(* Logix 5000 project; controller CIP_Sync_Essentials_Sample_Project_2_1 vendor 1 type 14 code 156 rev 34.11; software revision 34.01 *)

TASK IOTask (task) : IOProgram
TASK MainTask (periodic, rate 3 ms, priority 10, watchdog 500 ms) : MainProgram

MODULES
   Local : vendor 1 type 14 code 156 (Compact 0, rev 34.11)
      Essentials_1 : vendor 452 type 43 code 30 (Ethernet 192.168.1.12, rev 1.3, StandardDataDriven RPI 3 ms)
END_MODULES

TYPE CIP_AxisInputData :
STRUCT
   Data : SINT[10];
END_STRUCT
END_TYPE

TYPE CIP_AxisOutputData :
STRUCT
   Data : SINT[14];
END_STRUCT
END_TYPE

TYPE CIP_Control :
STRUCT
   Switch_On : BOOL;
   Disable_Voltage : BOOL;
   Quick_Stop : BOOL;
   Enable_Operation : BOOL;
   Op_Mode_Specific_4 : BOOL;   // Home Start or Follow Position bit, depending on on whether bit 11 (Mode Home) or bit 12 (C
   Op_Mode_Specific_5 : BOOL;   // Unused
   Op_Mode_Specific_6 : BOOL;   // Unused
   Reset_Fault : BOOL;
   Pause_Halt : BOOL;
   Op_Mode_Specific_9 : BOOL;   // Unused
   Reserved_10 : BOOL;
   Manu_Specific_11 : BOOL;   // Mode Home bit
   Manu_Specific_12 : BOOL;   // Mode Cyclic Position bit
   Manu_Specific_13 : BOOL;   // Unused
   Manu_Specific_14 : BOOL;   // Unused
   Manu_Specific_15 : BOOL;   // Unused
END_STRUCT
END_TYPE

TYPE CIP_DynamicMap :
STRUCT
   Input : CIP_MapInputData;   // Map data from the drive
   Output : CIP_MapOutputData;   // Map data to the drive
END_STRUCT
END_TYPE

TYPE CIP_MapInputData :   // Map data received from the drive
STRUCT
   Data : SINT[40];
END_STRUCT
END_TYPE

TYPE CIP_MapOutputData :   // Map data going to drive
STRUCT
   Data : SINT[32];
END_STRUCT
END_TYPE

TYPE CIP_Status :   // All connections to the drive ethernet module are established and data is successfully transferring.
STRUCT
   Ready_To_Switch_On : BOOL;
   Switched_On : BOOL;
   Operation_Enabled : BOOL;
   Fault : BOOL;
   Voltage_Enabled : BOOL;
   Quick_Stop : BOOL;
   Switch_On_Disabled : BOOL;
   Warning : BOOL;
   STO_Active : BOOL;
   Remote : BOOL;
   Target_Reached : BOOL;
   Internal_Limit_Active : BOOL;
   Op_Mode_Specific_12 : BOOL;   // Home Attained bit
   Op_Mode_Specific_13 : BOOL;   // Homing/Cyclic Position Error bit
   Manu_Specific_14 : BOOL;   // Motion Mode bit (0 for Homing, 1 for Cyclic Position)
   Manu_Specific_15 : BOOL;   // Following Position bit (for Cyclic Position mode)
END_STRUCT
END_TYPE

ADD_ON_INSTRUCTION CIP_Axis_Disable   (* revision 2.1, ExecutePrescan, ExecuteEnableInFalse *)
// Disable CIP Sync Axis
VAR_OUTPUT
   DN : BOOL; {access Read Only, visible}   // Command Successful
   ER : BOOL; {access Read Only, visible}   // Error
END_VAR
VAR_IN_OUT
   Axis : CIP_Axis; {required}
END_VAR
VAR_OUTPUT
   Error_Code : SINT; {access Read Only, visible}
END_VAR
VAR_IN_OUT
   Error_Description : STRING; {required}
END_VAR
VAR
   CommandTimeout : TIMER;   // Timeout Timer
   Step : SINT; {access None}
   ErrorEnumeratedValues : STRING[2] := ([0] := 'No Error', [1] := 'Command Timeout'); {access None}
END_VAR

ROUTINE EnableInFalse   (* ladder *)
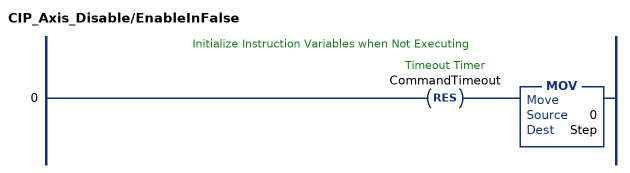
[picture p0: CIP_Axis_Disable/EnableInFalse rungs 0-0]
   // Initialize Instruction Variables when Not Executing
   0: RES(CommandTimeout)MOV(0,Step);
END_ROUTINE

ROUTINE Logic   (* ladder *)
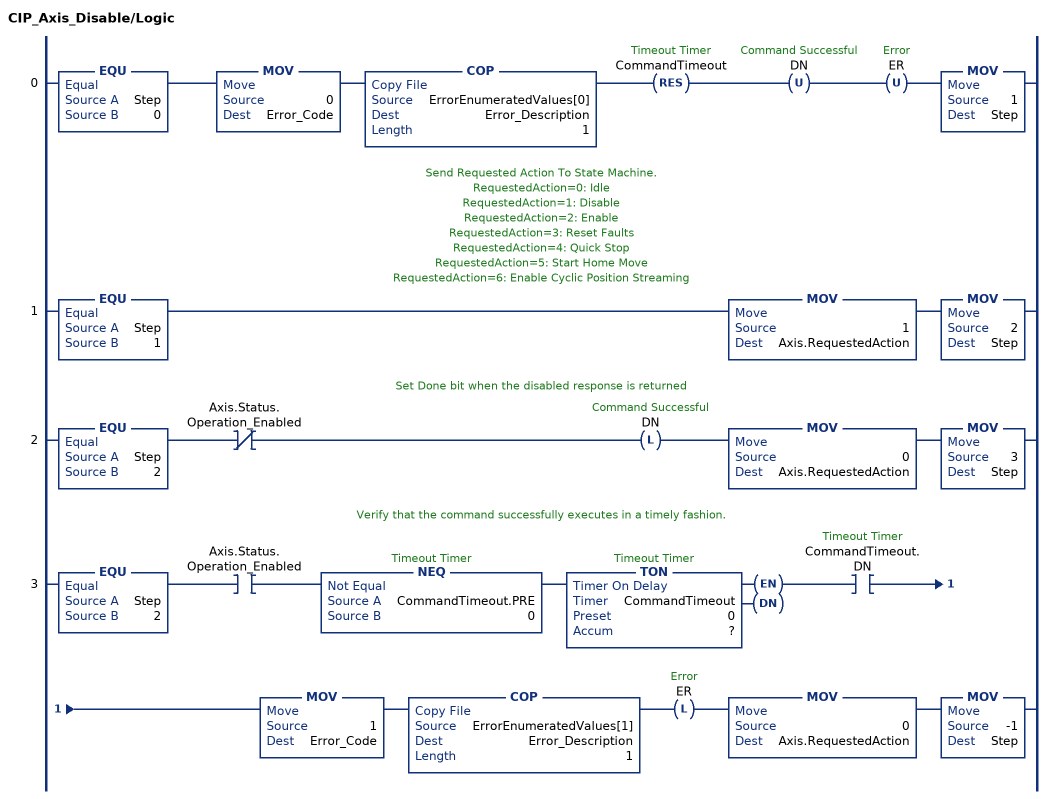
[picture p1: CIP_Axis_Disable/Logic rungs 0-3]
   0: EQU(Step,0)MOV(0,Error_Code)COP(ErrorEnumeratedValues[0],Error_Description,1)RES(CommandTimeout)OTU(DN)OTU(ER)MOV(1,Step);
   // Send Requested Action To State Machine.
   // RequestedAction=0: Idle
   // RequestedAction=1: Disable
   // RequestedAction=2: Enable
   // RequestedAction=3: Reset Faults
   // RequestedAction=4: Quick Stop
   // RequestedAction=5: Start Home Move
   // RequestedAction=6: Enable Cyclic Position Streaming
   1: EQU(Step,1)MOV(1,Axis.RequestedAction)MOV(2,Step);
   // Set Done bit when the disabled response is returned
   2: EQU(Step,2)XIO(Axis.Status.Operation_Enabled)OTL(DN)MOV(0,Axis.RequestedAction)MOV(3,Step);
   // Verify that the command successfully executes in a timely fashion.
   3: EQU(Step,2)XIC(Axis.Status.Operation_Enabled)NEQ(CommandTimeout.PRE,0)TON(CommandTimeout,?,?)XIC(CommandTimeout.DN)MOV(1,Error_Code)COP(ErrorEnumeratedValues[1],Error_Description,1)OTL(ER)MOV(0,Axis.RequestedAction)MOV(-1,Step);
END_ROUTINE

ROUTINE Prescan   (* ladder *)
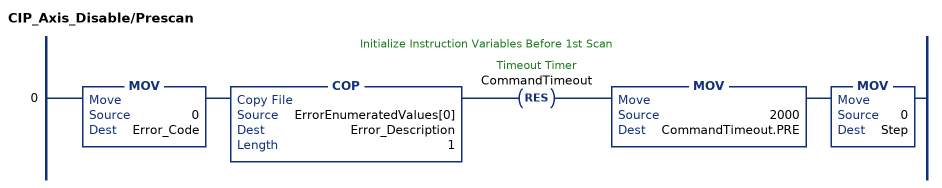
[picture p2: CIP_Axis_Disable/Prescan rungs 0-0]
   // Initialize Instruction Variables Before 1st Scan
   0: MOV(0,Error_Code)COP(ErrorEnumeratedValues[0],Error_Description,1)RES(CommandTimeout)MOV(2000,CommandTimeout.PRE)MOV(0,Step);
END_ROUTINE
END_ADD_ON_INSTRUCTION

ADD_ON_INSTRUCTION CIP_Axis_Disable_Streaming   (* revision 2.1, ExecutePrescan, ExecuteEnableInFalse *)
// CIP Sync Axis Disable Streaming
VAR_OUTPUT
   DN : BOOL; {access Read Only, visible}   // Command Successful
   ER : BOOL; {access Read Only, visible}   // Error
END_VAR
VAR_IN_OUT
   Axis : CIP_Axis; {required}
END_VAR
VAR_OUTPUT
   Error_Code : SINT; {access Read Only, visible}
END_VAR
VAR_IN_OUT
   Error_Description : STRING; {required}
END_VAR
VAR
   CommandTimeout : TIMER := (PRE := 2000); {access None}   // Timeout Timer
   Step : SINT; {access None}
   ErrorEnumeratedValues : STRING[2] := ([0] := 'No Error', [1] := 'Command Timeout'); {access None}
END_VAR

ROUTINE EnableInFalse   (* ladder *)
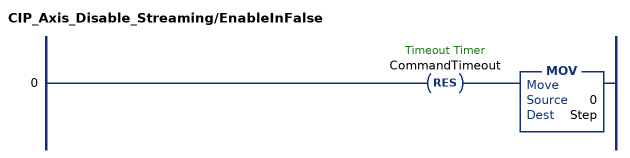
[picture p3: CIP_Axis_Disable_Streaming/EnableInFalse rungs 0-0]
   0: RES(CommandTimeout)MOV(0,Step);
END_ROUTINE

ROUTINE Logic   (* ladder *)
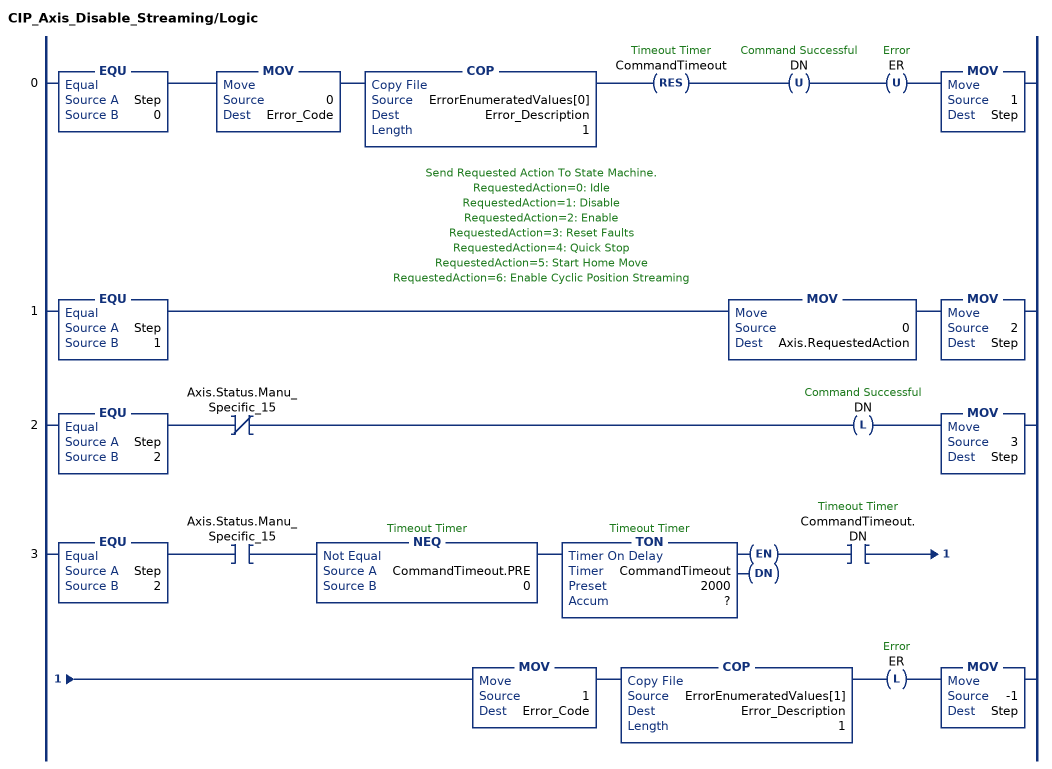
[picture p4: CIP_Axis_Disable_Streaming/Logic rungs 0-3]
   0: EQU(Step,0)MOV(0,Error_Code)COP(ErrorEnumeratedValues[0],Error_Description,1)RES(CommandTimeout)OTU(DN)OTU(ER)MOV(1,Step);
   // Send Requested Action To State Machine.
   // RequestedAction=0: Idle
   // RequestedAction=1: Disable
   // RequestedAction=2: Enable
   // RequestedAction=3: Reset Faults
   // RequestedAction=4: Quick Stop
   // RequestedAction=5: Start Home Move
   // RequestedAction=6: Enable Cyclic Position Streaming
   1: EQU(Step,1)MOV(0,Axis.RequestedAction)MOV(2,Step);
   2: EQU(Step,2)XIO(Axis.Status.Manu_Specific_15)OTL(DN)MOV(3,Step);
   3: EQU(Step,2)XIC(Axis.Status.Manu_Specific_15)NEQ(CommandTimeout.PRE,0)TON(CommandTimeout,?,?)XIC(CommandTimeout.DN)MOV(1,Error_Code)COP(ErrorEnumeratedValues[1],Error_Description,1)OTL(ER)MOV(-1,Step);
END_ROUTINE

ROUTINE Prescan   (* ladder *)
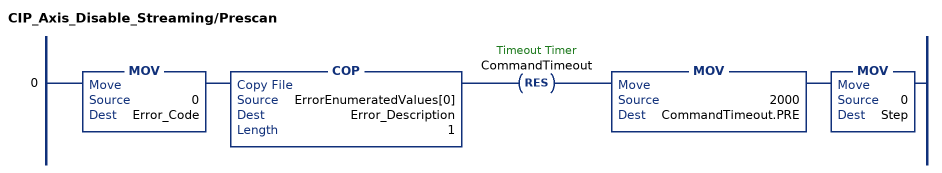
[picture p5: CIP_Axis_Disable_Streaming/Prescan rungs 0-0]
   0: MOV(0,Error_Code)COP(ErrorEnumeratedValues[0],Error_Description,1)RES(CommandTimeout)MOV(2000,CommandTimeout.PRE)MOV(0,Step);
END_ROUTINE
END_ADD_ON_INSTRUCTION

ADD_ON_INSTRUCTION CIP_Axis_Enable   (* revision 2.1, ExecutePrescan, ExecuteEnableInFalse *)
// Enables CIP Sync Axis
// Revision note:
// Bugfix: Added check of Axis.Status.Quick_Stop bit for confirming completion
VAR_OUTPUT
   DN : BOOL; {access Read Only, visible}   // Command Successful
   ER : BOOL; {access Read Only, visible}   // Error
END_VAR
VAR_IN_OUT
   Axis : CIP_Axis; {required}
END_VAR
VAR_OUTPUT
   Error_Code : SINT; {access Read Only, visible}
END_VAR
VAR_IN_OUT
   Error_Description : STRING; {required}
END_VAR
VAR
   CommandTimeout : TIMER := (PRE := 2000);   // Timeout Timer
   Step : SINT; {access None}
   ErrorEnumeratedValues : STRING[3] := ([0] := 'No Error', [1] := 'Command Timeout', [2] := 'Axis Faulted'); {access None}
END_VAR

ROUTINE EnableInFalse   (* ladder *)
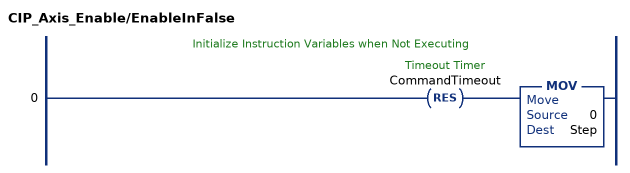
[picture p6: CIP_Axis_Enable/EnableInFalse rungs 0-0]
   // Initialize Instruction Variables when Not Executing
   0: RES(CommandTimeout)MOV(0,Step);
END_ROUTINE

ROUTINE Logic   (* ladder *)
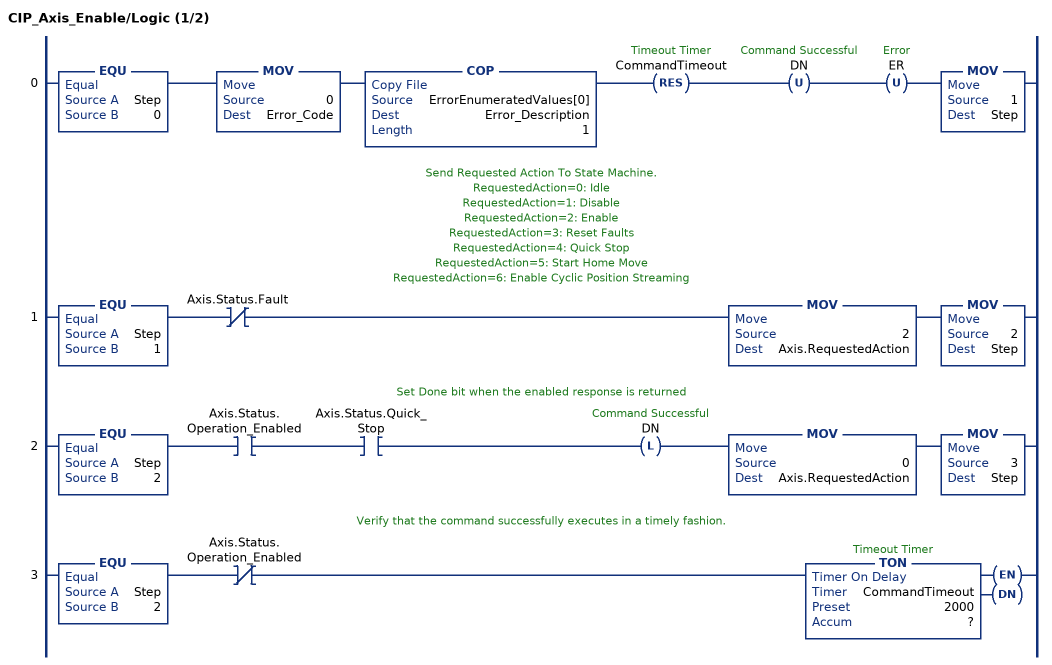
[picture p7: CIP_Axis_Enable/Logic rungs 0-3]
   0: EQU(Step,0)MOV(0,Error_Code)COP(ErrorEnumeratedValues[0],Error_Description,1)RES(CommandTimeout)OTU(DN)OTU(ER)MOV(1,Step);
   // Send Requested Action To State Machine.
   // RequestedAction=0: Idle
   // RequestedAction=1: Disable
   // RequestedAction=2: Enable
   // RequestedAction=3: Reset Faults
   // RequestedAction=4: Quick Stop
   // RequestedAction=5: Start Home Move
   // RequestedAction=6: Enable Cyclic Position Streaming
   1: EQU(Step,1)XIO(Axis.Status.Fault)MOV(2,Axis.RequestedAction)MOV(2,Step);
   // Set Done bit when the enabled response is returned
   2: EQU(Step,2)XIC(Axis.Status.Operation_Enabled)XIC(Axis.Status.Quick_Stop)OTL(DN)MOV(0,Axis.RequestedAction)MOV(3,Step);
   // Verify that the command successfully executes in a timely fashion.
   3: EQU(Step,2)XIO(Axis.Status.Operation_Enabled)TON(CommandTimeout,?,?);
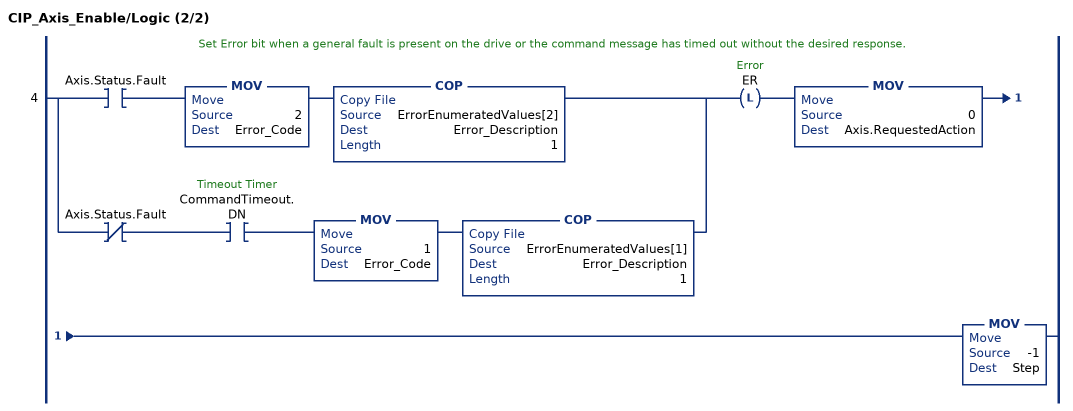
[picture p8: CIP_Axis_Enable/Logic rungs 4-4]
   // Set Error bit when a general fault is present on the drive or the command message has timed out without the desired response.
   4: [XIC(Axis.Status.Fault) MOV(2,Error_Code) COP(ErrorEnumeratedValues[2],Error_Description,1) ,XIO(Axis.Status.Fault) XIC(CommandTimeout.DN) MOV(1,Error_Code) COP(ErrorEnumeratedValues[1],Error_Description,1) ]OTL(ER)MOV(0,Axis.RequestedAction)MOV(-1,Step);
END_ROUTINE

ROUTINE Prescan   (* ladder *)
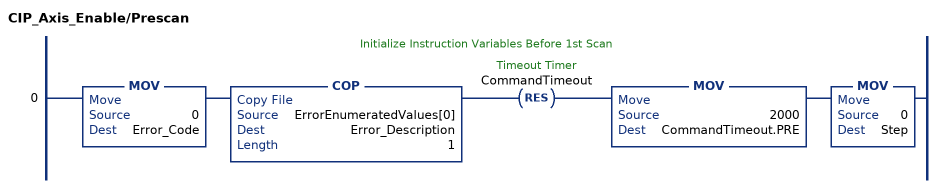
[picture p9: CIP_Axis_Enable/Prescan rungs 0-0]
   // Initialize Instruction Variables Before 1st Scan
   0: MOV(0,Error_Code)COP(ErrorEnumeratedValues[0],Error_Description,1)RES(CommandTimeout)MOV(2000,CommandTimeout.PRE)MOV(0,Step);
END_ROUTINE
END_ADD_ON_INSTRUCTION

ADD_ON_INSTRUCTION CIP_Axis_Enable_Streaming   (* revision 2.1, ExecutePrescan, ExecuteEnableInFalse *)
// CIP Sync Axis Enable Streaming
VAR_OUTPUT
   DN : BOOL; {access Read Only, visible}   // Command Successful
   ER : BOOL; {access Read Only, visible}   // Error
END_VAR
VAR_IN_OUT
   Axis : CIP_Axis; {required}
END_VAR
VAR_OUTPUT
   Error_Code : SINT; {visible}
END_VAR
VAR_IN_OUT
   Error_Description : STRING; {required}
END_VAR
VAR
   CommandTimeout : TIMER := (PRE := 2000); {access None}   // Timeout Timer
   Step : SINT; {access None}
   ErrorEnumeratedValues : STRING[5] := ([0] := 'No Error', [1] := 'Command Timeout', [2] := 'Axis Faulted', [3] := 'Home Not Attained', [4] := 'Axis Not Enabled'); {access None}
END_VAR

ROUTINE EnableInFalse   (* ladder *)
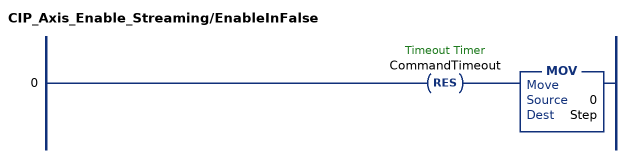
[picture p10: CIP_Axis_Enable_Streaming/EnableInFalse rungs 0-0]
   0: RES(CommandTimeout)MOV(0,Step);
END_ROUTINE

ROUTINE Logic   (* ladder *)
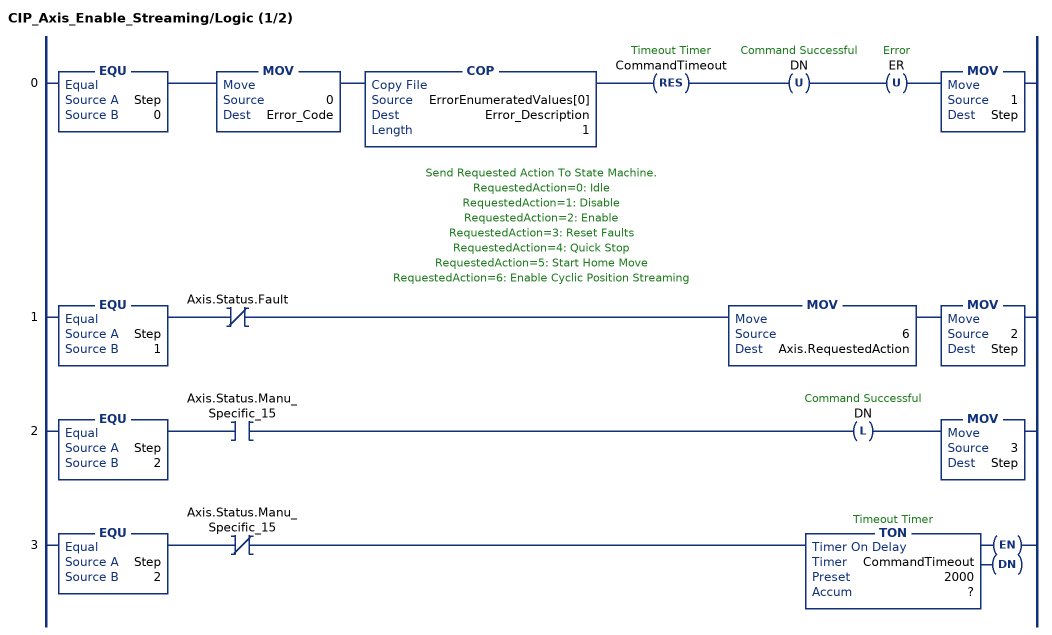
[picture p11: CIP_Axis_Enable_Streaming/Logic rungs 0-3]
   0: EQU(Step,0)MOV(0,Error_Code)COP(ErrorEnumeratedValues[0],Error_Description,1)RES(CommandTimeout)OTU(DN)OTU(ER)MOV(1,Step);
   // Send Requested Action To State Machine.
   // RequestedAction=0: Idle
   // RequestedAction=1: Disable
   // RequestedAction=2: Enable
   // RequestedAction=3: Reset Faults
   // RequestedAction=4: Quick Stop
   // RequestedAction=5: Start Home Move
   // RequestedAction=6: Enable Cyclic Position Streaming
   1: EQU(Step,1)XIO(Axis.Status.Fault)MOV(6,Axis.RequestedAction)MOV(2,Step);
   2: EQU(Step,2)XIC(Axis.Status.Manu_Specific_15)OTL(DN)MOV(3,Step);
   3: EQU(Step,2)XIO(Axis.Status.Manu_Specific_15)TON(CommandTimeout,?,?);
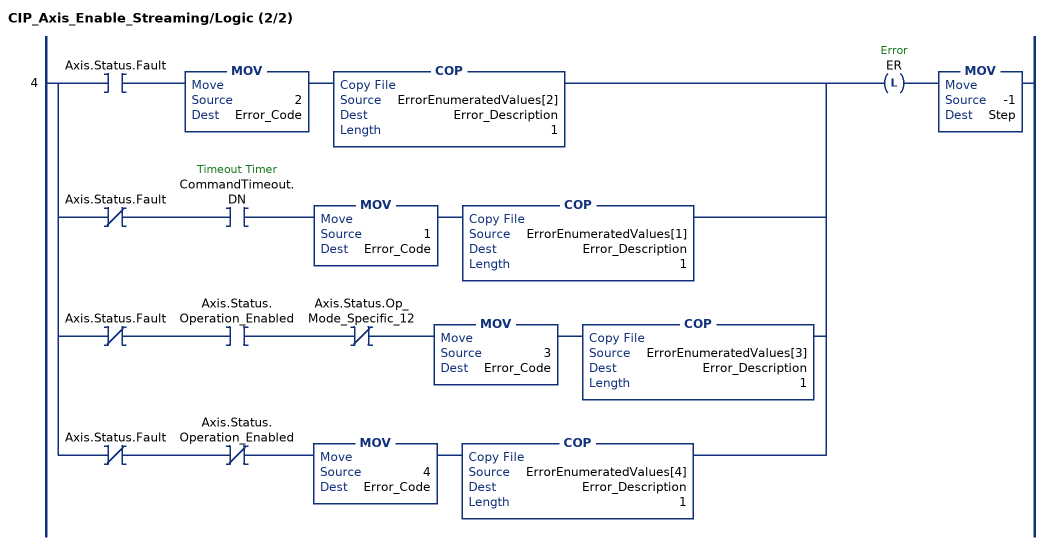
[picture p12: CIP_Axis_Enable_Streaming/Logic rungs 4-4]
   4: [XIC(Axis.Status.Fault) MOV(2,Error_Code) COP(ErrorEnumeratedValues[2],Error_Description,1) ,XIO(Axis.Status.Fault) XIC(CommandTimeout.DN) MOV(1,Error_Code) COP(ErrorEnumeratedValues[1],Error_Description,1) ,XIO(Axis.Status.Fault) XIC(Axis.Status.Operation_Enabled) XIO(Axis.Status.Op_Mode_Specific_12) MOV(3,Error_Code) COP(ErrorEnumeratedValues[3],Error_Description,1) ,XIO(Axis.Status.Fault) XIO(Axis.Status.Operation_Enabled) MOV(4,Error_Code) COP(ErrorEnumeratedValues[4],Error_Description,1) ]OTL(ER)MOV(-1,Step);
END_ROUTINE

ROUTINE Prescan   (* ladder *)
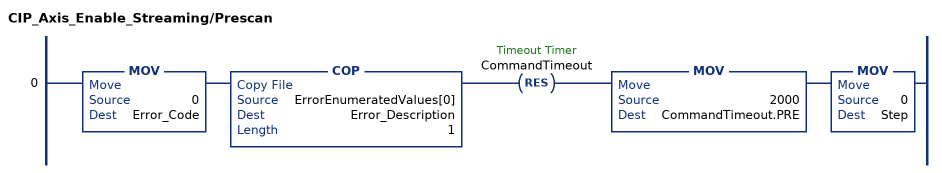
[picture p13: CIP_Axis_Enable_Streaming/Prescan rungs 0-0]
   0: MOV(0,Error_Code)COP(ErrorEnumeratedValues[0],Error_Description,1)RES(CommandTimeout)MOV(2000,CommandTimeout.PRE)MOV(0,Step);
END_ROUTINE
END_ADD_ON_INSTRUCTION

ADD_ON_INSTRUCTION CIP_Axis_Fault_Reset   (* revision 2.1, ExecutePrescan, ExecuteEnableInFalse *)
// CIP Sync Axis Fault Reset
VAR_OUTPUT
   DN : BOOL; {access Read Only, visible}   // Command Successful
   ER : BOOL; {access Read Only, visible}   // Error
END_VAR
VAR_IN_OUT
   Axis : CIP_Axis; {required}
END_VAR
VAR_OUTPUT
   Error_Code : SINT; {access Read Only, visible}
END_VAR
VAR_IN_OUT
   Error_Description : STRING; {required}
END_VAR
VAR
   Step : SINT;
   CommandTimeout : TIMER := (PRE := 2000); {access None}
   ErrorEnumeratedValues : STRING[2] := ([0] := 'No Error', [1] := 'Command Timeout'); {access None}
END_VAR

ROUTINE EnableInFalse   (* ladder *)
// EnableIn_False
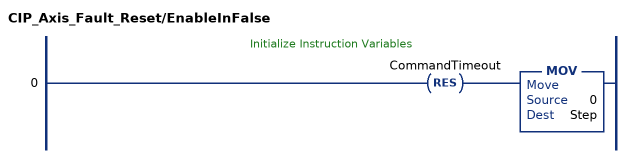
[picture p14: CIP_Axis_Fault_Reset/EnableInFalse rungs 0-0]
   // Initialize Instruction Variables
   0: RES(CommandTimeout)MOV(0,Step);
END_ROUTINE

ROUTINE Logic   (* ladder *)
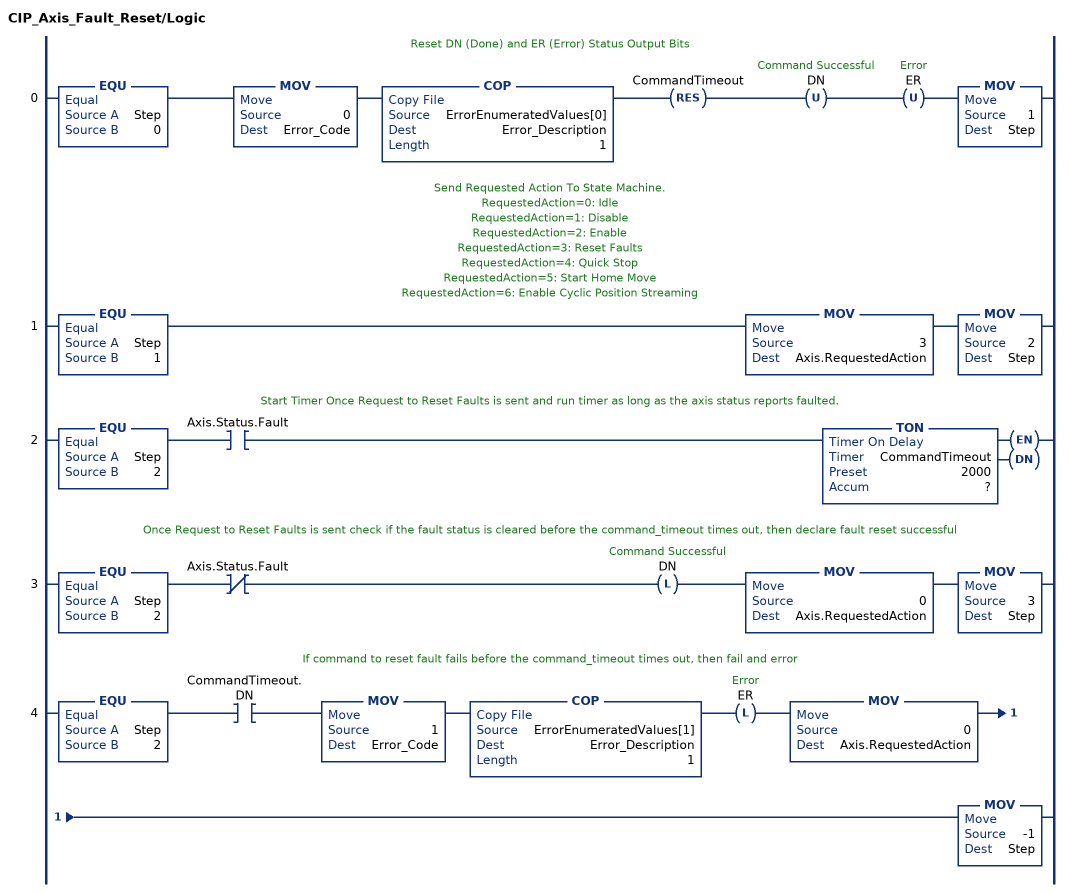
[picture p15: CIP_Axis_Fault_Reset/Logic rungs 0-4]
   // Reset DN (Done) and ER (Error) Status Output Bits
   0: EQU(Step,0)MOV(0,Error_Code)COP(ErrorEnumeratedValues[0],Error_Description,1)RES(CommandTimeout)OTU(DN)OTU(ER)MOV(1,Step);
   // Send Requested Action To State Machine.
   // RequestedAction=0: Idle
   // RequestedAction=1: Disable
   // RequestedAction=2: Enable
   // RequestedAction=3: Reset Faults
   // RequestedAction=4: Quick Stop
   // RequestedAction=5: Start Home Move
   // RequestedAction=6: Enable Cyclic Position Streaming
   1: EQU(Step,1)MOV(3,Axis.RequestedAction)MOV(2,Step);
   // Start Timer Once Request to Reset Faults is sent and run timer as long as the axis status reports faulted.
   2: EQU(Step,2)XIC(Axis.Status.Fault)TON(CommandTimeout,?,?);
   // Once Request to Reset Faults is sent check if the fault status is cleared before the command_timeout times out, then declare fault reset successful
   3: EQU(Step,2)XIO(Axis.Status.Fault)OTL(DN)MOV(0,Axis.RequestedAction)MOV(3,Step);
   // If command to reset fault fails before the command_timeout times out, then fail and error
   4: EQU(Step,2)XIC(CommandTimeout.DN)MOV(1,Error_Code)COP(ErrorEnumeratedValues[1],Error_Description,1)OTL(ER)MOV(0,Axis.RequestedAction)MOV(-1,Step);
END_ROUTINE

ROUTINE Prescan   (* ladder *)
// Prescan
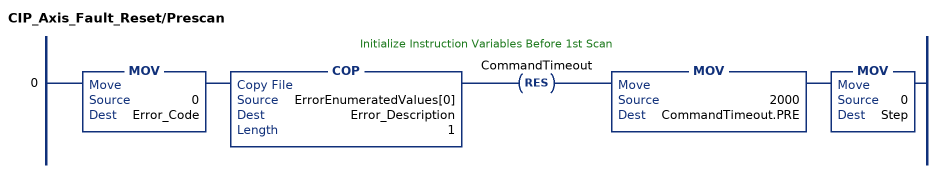
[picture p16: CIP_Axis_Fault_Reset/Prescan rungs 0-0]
   // Initialize Instruction Variables Before 1st Scan
   0: MOV(0,Error_Code)COP(ErrorEnumeratedValues[0],Error_Description,1)RES(CommandTimeout)MOV(2000,CommandTimeout.PRE)MOV(0,Step);
END_ROUTINE
END_ADD_ON_INSTRUCTION

ADD_ON_INSTRUCTION CIP_Axis_Home   (* revision 2.1, ExecutePrescan, ExecuteEnableInFalse *)
// Home Axis
VAR_OUTPUT
   DN : BOOL; {access Read Only, visible}   // Command Successfully Initiated
   ER : BOOL; {access Read Only, visible}   // Error
   IP : BOOL; {access Read Only, visible}   // Command in Process
   PC : BOOL; {access Read Only, visible}   // Command Process Complete
END_VAR
VAR_IN_OUT
   Axis : CIP_Axis; {required}
END_VAR
VAR_INPUT
   TimeOut_mS : DINT; {required}
END_VAR
VAR_OUTPUT
   Error_Code : SINT; {access Read Only, visible}
END_VAR
VAR_IN_OUT
   Error_Description : STRING; {required}
END_VAR
VAR
   Step : SINT;
   ErrorEnumeratedValues : STRING[7] := ([0] := 'No Error', [1] := 'Command Timeout', [2] := 'Axis Faulted', [3] := 'Axis Not Enabled', [4] := 'User Homing Timeout_mS Exceeded', [5] := 'Axis Homing Error Occurred', [6] := 'Homing Not Allowed While Streaming Active'); {access None}
   TimeOut : TIMER := (PRE := 5000); {access None}
   Command_Delay : TIMER := (PRE := 50); {access None}   // Delay after command to home is sent
   Command_Timeout : TIMER := (PRE := 2000); {access None}
END_VAR

ROUTINE EnableInFalse   (* ladder *)
// EnableIn_False
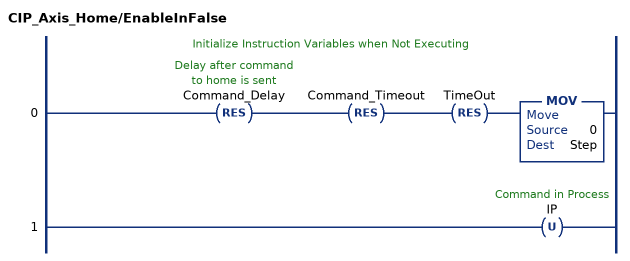
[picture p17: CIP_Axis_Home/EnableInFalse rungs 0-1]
   // Initialize Instruction Variables when Not Executing
   0: RES(Command_Delay)RES(Command_Timeout)RES(TimeOut)MOV(0,Step);
   1: OTU(IP);
END_ROUTINE
